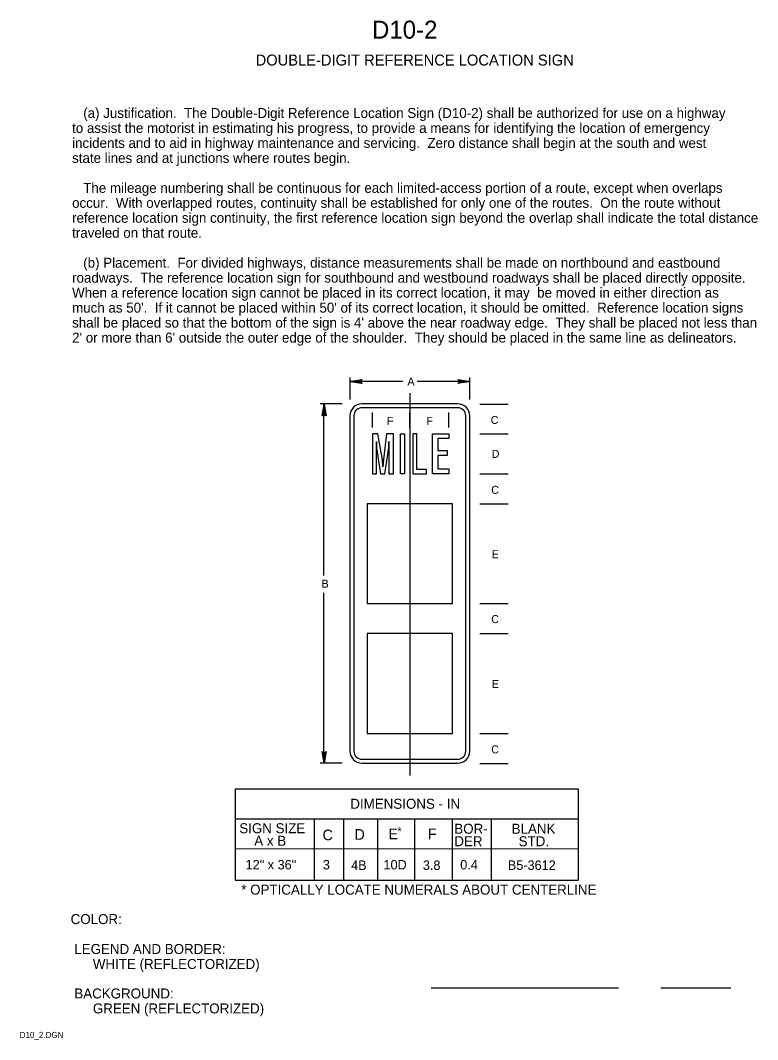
# Model space of a CAD drawing. Extents: x 0.013 to 0.197, y 0.004 to 0.259.
import ezdxf

# ---------------------------------------------------------------- set-up
doc = ezdxf.new("R2010")
doc.units = 0
for name, color, linetype in [('1', 7, 'Continuous'), ('2', 7, 'Continuous'), ('3', 7, 'Continuous')]:
    doc.layers.add(name, color=color, linetype=linetype)

# ---------------------------------------------------------------- blocks, each defined once
blk = doc.blocks.new('RARROW')
at = {"layer": '3'}
for p, q in [((-2.156, 0.285), (-2.2665, 0.384625)), ((-2.2665, 0.384625), (0, 0)), ((0, 0), (-2.2665, -0.379125)), ((-2.156, 0.285), (-2.075625, 0.12075)), ((0, 0), (-2.156, 0.285)), ((-2.14975, -0.2705), (0, 0)), ((-2.075625, 0.12075), (0, 0)), ((0, 0), (-2.074, -0.108)), ((-2.2665, -0.379125), (-2.14975, -0.2705)), ((-2.074, -0.108), (-2.14975, -0.2705))]:
    blk.add_line(p, q, dxfattribs=at)

msp = doc.modelspace()

# ---------------------------------------------------------------- linework, layer by layer
at = {"layer": '1'}
for p, q in [((0.11544, 0.01695), (0.16242, 0.01695)), ((0.17295, 0.01695), (0.19056, 0.01695))]:
    msp.add_line(p, q, dxfattribs=at)
at = {"layer": '2'}
for p, q in [((0.09513, 0.16427), (0.09513, 0.16977)), ((0.10838, 0.16877), (0.09513, 0.16877)), ((0.12513, 0.16877), (0.11194, 0.16877)), ((0.12513, 0.16427), (0.12513, 0.16977)), ((0.09314, 0.16317), (0.08764, 0.16317)), ((0.08858, 0.12017), (0.08858, 0.16317)), ((0.10075, 0.15725), (0.10075, 0.161)), ((0.11013, 0.15725), (0.11013, 0.161)), ((0.11988, 0.15725), (0.11988, 0.161)), ((0.12763, 0.16312), (0.13475, 0.16312)), ((0.12763, 0.15563), (0.13475, 0.15563)), ((0.12763, 0.14563), (0.13475, 0.14563)), ((0.09943, 0.13813), (0.09943, 0.11313)), ((0.12083, 0.13813), (0.09943, 0.13813)), ((0.12083, 0.11313), (0.12083, 0.13813)), ((0.12763, 0.13812), (0.13475, 0.13812)), ((0.08858, 0.07317), (0.08858, 0.11582)), ((0.09943, 0.11313), (0.12083, 0.11313)), ((0.12763, 0.11313), (0.13475, 0.11313)), ((0.09943, 0.10563), (0.09943, 0.08063)), ((0.12083, 0.10563), (0.09943, 0.10563)), ((0.12083, 0.08063), (0.12083, 0.10563)), ((0.12763, 0.10562), (0.13475, 0.10562)), ((0.09943, 0.08063), (0.12083, 0.08063)), ((0.12763, 0.08063), (0.13475, 0.08063)), ((0.09314, 0.07317), (0.08764, 0.07317)), ((0.12763, 0.07312), (0.13475, 0.07312))]:
    msp.add_line(p, q, dxfattribs=at)
for points in [[(0.10075, 0.15563), (0.10075, 0.14563), (0.10175, 0.14563), (0.10175, 0.152), (0.10175, 0.15375), (0.10175, 0.15213), (0.10275, 0.14563), (0.10388, 0.14563), (0.10487, 0.15213), (0.10487, 0.15375), (0.10487, 0.152), (0.10487, 0.14563), (0.106, 0.14563), (0.106, 0.15563), (0.10425, 0.15563), (0.1035, 0.14925), (0.10338, 0.14738), (0.10325, 0.14925), (0.10213, 0.15563), (0.10075, 0.15563)], [(0.10775, 0.14563), (0.10775, 0.15563), (0.10875, 0.15563), (0.10875, 0.14563), (0.10775, 0.14563)], [(0.11088, 0.15563), (0.11088, 0.14563), (0.11425, 0.14563), (0.11425, 0.14675), (0.11188, 0.14675), (0.11188, 0.15563), (0.11088, 0.15563)], [(0.11575, 0.14563), (0.11575, 0.15563), (0.11988, 0.15563), (0.11988, 0.1545), (0.11713, 0.1545), (0.11713, 0.1515), (0.1195, 0.1515), (0.1195, 0.15025), (0.11713, 0.15025), (0.11713, 0.14688), (0.11988, 0.14688), (0.11988, 0.14563), (0.11575, 0.14563)]]:
    msp.add_lwpolyline(points, dxfattribs=at)
at = {"layer": '3'}
for p, q in [((0.11011, 0.16582), (0.11011, 0.07008)), ((0.12211, 0.16317), (0.09811, 0.16317)), ((0.12211, 0.16217), (0.09811, 0.16217)), ((0.09511, 0.16017), (0.09511, 0.07617)), ((0.09611, 0.16017), (0.09611, 0.07617)), ((0.12411, 0.07617), (0.12411, 0.16017)), ((0.12511, 0.07617), (0.12511, 0.16017)), ((0.09811, 0.07417), (0.12211, 0.07417)), ((0.09811, 0.07317), (0.12211, 0.07317)), ((0.06635, 0.06675), (0.15224, 0.06677)), ((0.06636, 0.06677), (0.06636, 0.04388)), ((0.15224, 0.06677), (0.15224, 0.0439)), ((0.15224, 0.05914), (0.06635, 0.05913)), ((0.08611, 0.05902), (0.08611, 0.04388)), ((0.09349, 0.05915), (0.09349, 0.04388)), ((0.10199, 0.05915), (0.10199, 0.04388)), ((0.11124, 0.05917), (0.11124, 0.0439)), ((0.11124, 0.05917), (0.11124, 0.0439)), ((0.12074, 0.05917), (0.12074, 0.0439)), ((0.13049, 0.05917), (0.13049, 0.0439)), ((0.06635, 0.05175), (0.15224, 0.05177)), ((0.06635, 0.04388), (0.15224, 0.04389))]:
    msp.add_line(p, q, dxfattribs=at)
for centre, radius, start, end in [((0.09811, 0.16017), 0.003, 90, 180), ((0.09811, 0.16017), 0.002, 90, 180), ((0.12211, 0.16017), 0.003, 0, 90), ((0.12211, 0.16017), 0.002, 0, 90), ((0.09811, 0.07617), 0.003, 180, 270), ((0.09811, 0.07617), 0.002, 180, 270), ((0.12211, 0.07617), 0.003, 270, 0), ((0.12211, 0.07617), 0.002, 270, 0)]:
    msp.add_arc(centre, radius, start, end, dxfattribs=at)

# ---------------------------------------------------------------- block references
at = {"layer": '2', "xscale": 0.0013236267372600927, "yscale": 0.001309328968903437}
for p, rotation in [((0.09513, 0.16875), 180), ((0.08862, 0.16312), 90), ((0.08862, 0.07312), -90)]:
    msp.add_blockref('RARROW', p, dxfattribs=dict(at, rotation=rotation))
msp.add_blockref('RARROW', (0.12513, 0.16875), dxfattribs=at)

# ---------------------------------------------------------------- texts
at = {"layer": '1'}
for s, height, p in [('D10-2', 0.0045, (0.10063, 0.25462)), ('DOUBLE-DIGIT REFERENCE LOCATION SIGN', 0.0027503, (0.07148, 0.24788)), ('COLOR:', 0.0025, (0.02513, 0.03288)), (' LEGEND AND BORDER:', 0.0024998, (0.02513, 0.02538)), ('      WHITE (REFLECTORIZED)', 0.0024998, (0.02513, 0.02163)), (' BACKGROUND:', 0.0024998, (0.02513, 0.01425)), ('      GREEN (REFLECTORIZED)', 0.0024998, (0.02513, 0.0105)), ('D10_2.DGN', 0.0015, (0.01238, 0.00438))]:
    msp.add_text(s, height=height, dxfattribs=at).set_placement(p)
at = {"layer": '2'}
for s, height, p in [('   (a) Justification.  The Double-Digit Reference Location Sign (D10-2) shall be authorized for use on a highway', 0.00249975, (0.0255, 0.23475)), ('to assist the motorist in estimating his progress, to provide a means for identifying the location of emergency', 0.00249975, (0.0255, 0.231)), ('incidents and to aid in highway maintenance and servicing.  Zero distance shall begin at the south and west', 0.00249975, (0.0255, 0.22725)), ('state lines and at junctions where routes begin.', 0.0024998, (0.0255, 0.2235)), ('   The mileage numbering shall be continuous for each limited-access portion of a route, except when overlaps', 0.00249975, (0.0255, 0.216)), ('occur.  With overlapped routes, continuity shall be established for only one of the routes.  On the route without', 0.00249975, (0.0255, 0.21225)), ('reference location sign continuity, the first reference location sign beyond the overlap shall indicate the total distance ', 0.00249975, (0.0255, 0.2085)), ('traveled on that route.', 0.0024998, (0.0255, 0.20475)), ('   (b) Placement.  For divided highways, distance measurements shall be made on northbound and eastbound', 0.00249975, (0.0255, 0.19725)), ('roadways.  The reference location sign for southbound and westbound roadways shall be placed directly opposite. ', 0.00249975, (0.0255, 0.1935)), ('When a reference location sign cannot be placed in its correct location, it may  be moved in either direction as ', 0.00249975, (0.0255, 0.18975)), ("much as 50'.  If it cannot be placed within 50' of its correct location, it should be omitted.  Reference location signs ", 0.00249975, (0.0255, 0.186)), ("shall be placed so that the bottom of the sign is 4' above the near roadway edge.  They shall be placed not less than ", 0.00249975, (0.0255, 0.18225)), ("2' or more than 6' outside the outer edge of the shoulder.  They should be placed in the same line as delineators. ", 0.00249975, (0.0255, 0.1785)), ('A', 0.002, (0.1095, 0.16775)), ('F', 0.002, (0.10437, 0.15788)), ('F', 0.002, (0.11425, 0.15788)), ('C', 0.002, (0.13037, 0.15813)), ('D', 0.002, (0.13062, 0.14963)), ('C', 0.002, (0.1305, 0.14062)), ('E', 0.002, (0.13062, 0.1245)), ('B', 0.002, (0.088, 0.11713)), ('C', 0.002, (0.1305, 0.10825)), ('E', 0.002, (0.13062, 0.092)), ('C', 0.002, (0.1305, 0.07562))]:
    msp.add_text(s, height=height, dxfattribs=at).set_placement(p)
at = {"layer": '3'}
for s, height, p in [('DIMENSIONS - IN', 0.0024998, (0.0952, 0.06175)), ('SIGN SIZE', 0.0025, (0.06738, 0.05563)), ('C', 0.00267, (0.08825, 0.05387)), ('D', 0.00267, (0.09625, 0.054)), ('E', 0.00267, (0.10475, 0.05412)), ('*', 0.002, (0.107, 0.05513)), ('F', 0.00267, (0.11463, 0.05412)), ('BOR-', 0.0025, (0.12125, 0.0555)), ('BLANK', 0.0025, (0.13562, 0.0555)), ('A x B', 0.0025, (0.07113, 0.0525)), ('DER', 0.0025, (0.12125, 0.05237)), ('STD.', 0.0025, (0.13737, 0.05237)), ('12" x 36"', 0.002375, (0.06896, 0.04656)), ('3', 0.00238, (0.08831, 0.04656)), ('4B', 0.002375, (0.09539, 0.04644)), ('10D', 0.002375, (0.1035, 0.04656)), ('3.8', 0.002375, (0.11336, 0.04644)), ('0.4', 0.002375, (0.12273, 0.04656)), ('B5-3612', 0.002375, (0.13465, 0.04644)), ('* OPTICALLY LOCATE NUMERALS ABOUT CENTERLINE', 0.0024998, (0.06788, 0.04025))]:
    msp.add_text(s, height=height, dxfattribs=at).set_placement(p)

doc.saveas('drawing.dxf')
